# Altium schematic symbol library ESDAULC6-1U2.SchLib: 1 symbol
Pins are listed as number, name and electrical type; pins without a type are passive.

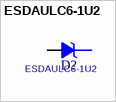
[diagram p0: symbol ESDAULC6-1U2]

## ESDAULC6-1U2
designator D?
footprint ST_ST0201
pins: 1 K, 2 A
